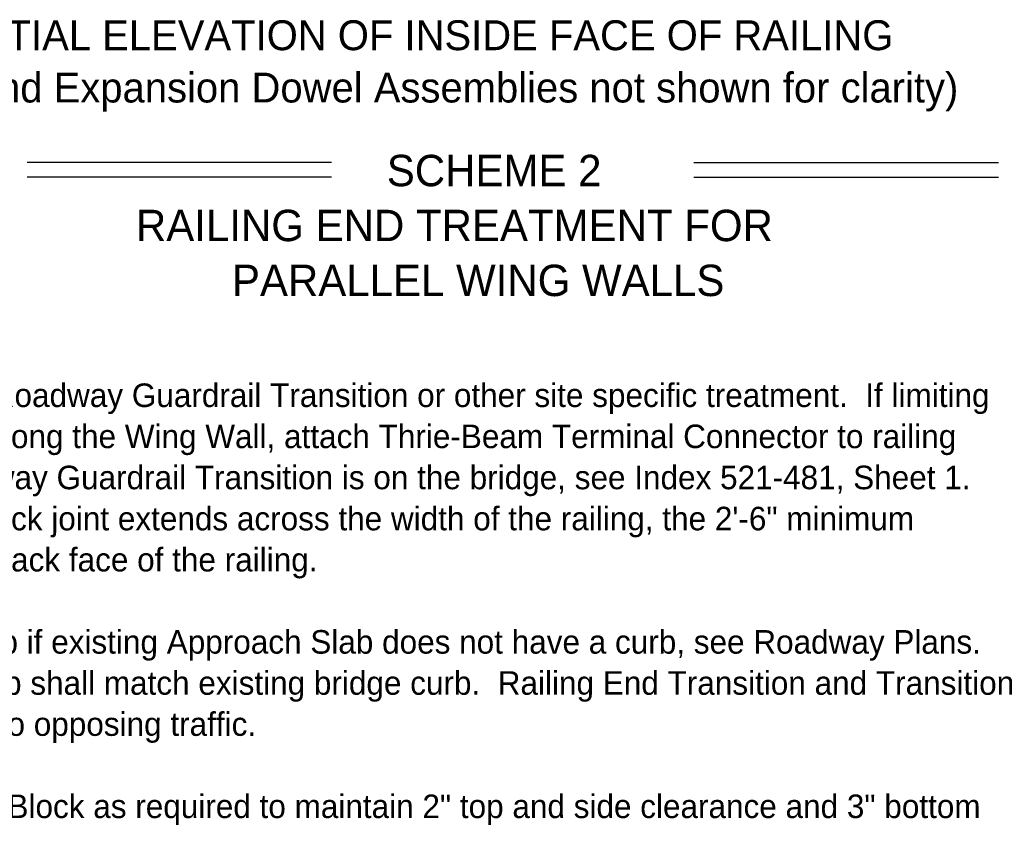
# Model space of a CAD drawing. Extents: x 1 to 39.2, y 0 to 26.
# Drawn here: x 26.61 to 35.1, y 0.72 to 7.62 of the extents above; entities that cross this region are included whole.
import ezdxf

# ---------------------------------------------------------------- set-up
doc = ezdxf.new("R2010")
doc.units = 0
doc.layers.add('Dimension', color=7, linetype='Continuous')

msp = doc.modelspace()

# ---------------------------------------------------------------- linework, layer by layer
at = {"layer": 'Dimension'}
for p, q in [((29.2756, 6.3968), (26.6686, 6.3968)), ((32.3768, 6.3968), (34.9839, 6.3968)), ((29.2756, 6.2714), (26.6686, 6.2714)), ((32.3768, 6.2714), (34.9839, 6.2714))]:
    msp.add_line(p, q, dxfattribs=at)

# ---------------------------------------------------------------- texts
for s, height, p in [('PARTIAL ELEVATION OF INSIDE FACE OF RAILING', 0.256001, (25.7899, 7.3583)), ('(Railing Reinforcing and Expansion Dowel Assemblies not shown for clarity)', 0.256001, (23.1474, 6.9103)), ('SCHEME 2', 0.2688, (29.7478, 6.1933)), ('RAILING END TREATMENT FOR ', 0.268801, (27.6006, 5.7229)), ('PARALLEL WING WALLS', 0.268801, (28.4224, 5.2525)), ('1.  See Roadway Plans for limiting station of Roadway Guardrail Transition or other site specific treatment.  If limiting ', 0.2016004, (21.017, 4.3025)), ('   station of Roadway Guardrail Transition is along the Wing Wall, attach Thrie-Beam Terminal Connector to railing ', 0.2016004, (21.017, 3.9505)), ('   as shown above.  If limiting station of Roadway Guardrail Transition is on the bridge, see Index 521-481, Sheet 1.  ', 0.2016004, (21.017, 3.5985)), ('   On skewed bridges, if the skew along the deck joint extends across the width of the railing, the 2\'-6" minimum ', 0.2016004, (21.017, 3.2465)), ('   dimension shall apply to both the front and back face of the railing. ', 0.2016, (21.017, 2.8945)), ('2. Provide Transition Block (as shown) or Curb if existing Approach Slab does not have a curb, see Roadway Plans.  ', 0.2016004, (21.017, 2.1905)), ('   Shape and height of Transition Block or Curb shall match existing bridge curb.  Railing End Transition and Transition ', 0.2016004, (21.017, 1.8385)), ('   Block may be omitted on trailing ends with no opposing traffic.', 0.2016, (21.017, 1.4865)), ('3. Field bend Dowel Bars 4L within Transition Block as required to maintain 2" top and side clearance and 3" bottom ', 0.2016004, (21.017, 0.7825))]:
    msp.add_text(s, height=height, dxfattribs=at).set_placement(p)

doc.saveas('drawing.dxf')
